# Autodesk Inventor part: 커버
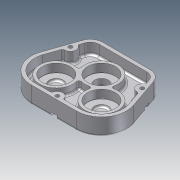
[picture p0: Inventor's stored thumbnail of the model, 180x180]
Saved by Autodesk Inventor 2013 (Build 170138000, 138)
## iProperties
Company: 한국ATC센터
Created: 2014-12
Part Number: 커버
Document SubType Name: Modeling
Designer: KYOUNG IL JANG
Density: 1 g/cm^3
Mass: 160.364 g
Surface Area: 512.085 cm^2
Volume: 160.364 cm^3
Material: 일반
Author: KYOUNG IL JANG
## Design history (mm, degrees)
sketch "스케치1"
  geometry: L1 (-66.565, -20.803)-(-47, 36); L2 (47, 36)-(66.565, -20.803); L3 (-32.527, -68.527)-(32.527, -68.527); L4 (-47, 36)-(47, 36); C1 r 28 at (0, 0); C2 r 18 at (-32.527, -32.527); C3 r 18 at (32.527, -32.527); A1 r 36 centre (-32.527, -32.527) between (-66.565, -20.803) and (-32.527, -68.527); A2 r 36 centre (32.527, -32.527) between (32.527, -68.527) and (66.565, -20.803); 2 further points
  constraints: 8 end point, 6 tangent, 5 centre point, 4 point on circle, 3 coincident, 2 equal radius, 1 equal length, 1 horizontal alignment, 1 midpoint, 1 vertical alignment
  dimensions: "d0" = 56 diameter of C1; "d1" = 36 diameter of C2; "d2" = 90 deg dimension on point (0, 0) C3.centre C2.centre; "d3" = 36 radius of A1; "d4" = 104.52691 distance between parallel lines of L3 L4 (derived); "d5" = 94 distance of L1.end L2.start; "d65" = 36 distance from line of point (0, 0) L4
extrude "돌출1" new body sketch "스케치1" distance "d6" = 25; taper "d7" = 0 deg
fillet "모깎기1" dims "d8" = 18
feature "쉘1" dims "d9" = 9, "d10" = 5
sketch "스케치2"
  geometry: C1 r 24 at (1.635, -63.527); C2 r 24 at (66.689, -63.527); C3 r 24 at (34.162, -31); 4 further points
  constraints: 4 coincident, 3 centre point, 1 equal radius
  dimensions: "d11" = 48 diameter of C3; "d12" = 48 diameter of C2
extrude "돌출2" join sketch "스케치2" distance "d13" = 11; taper "d14" = 0 deg
hole "구멍1" diameter "d17" = 20; stored, may be unused: countersink angle "d21" = 90 deg, drill point angle "d23" = 0 deg; dims "d15" = 10, "d16" = 10, "d18" = 6, "d19" = 40, "d20" = 12, "d22" = 3
hole "구멍2" diameter "d26" = 20; stored, may be unused: countersink angle "d30" = 90 deg, drill point angle "d32" = 0 deg; dims "d24" = 10, "d25" = 10, "d27" = 6, "d28" = 40, "d29" = 12, "d31" = 3
hole "구멍3" diameter "d35" = 20; stored, may be unused: countersink angle "d39" = 90 deg, drill point angle "d41" = 118 deg; dims "d33" = 10, "d34" = 10, "d36" = 6, "d37" = 40, "d38" = 12, "d40" = 3
sketch "스케치3"
  geometry: C1 r 15 at (0, 0); C2 r 20 at (0, 0); 1 further point
  constraints: 2 centre point, 2 coincident
  dimensions: "d42" = 40 diameter of C2; "d43" = 30 diameter of C1
extrude "돌출3" join sketch "스케치3" distance "d44" = 8; taper "d45" = 0 deg
feature "면 기울기1" dims angle "d46" = 10 deg
fillet "모깎기2" dims "d47" = 3
fillet "모깎기3" dims "d48" = 0.3
fillet "모깎기6" dims "d66" = 0.1
sketch "스케치4"
  geometry: L1 (-61.837, -22.432)-(-46.453, 22.233) reference; L2 (46.453, 22.233)-(61.837, -22.432) reference; L3 (32.527, -63.527)-(-32.527, -63.527) reference; L4 (-34.162, 31)-(34.162, 31) reference; A1 r 8 centre (51.7, 7) between (49.095, 14.564) and (54.305, -0.564); A2 r 8 centre (-51.7, 7) between (-54.305, -0.564) and (-49.095, 14.564); A3 r 8 centre (0, -63.527) between (8, -63.527) and (-8, -63.527)
  constraints: 8 point on line, 6 point on circle, 3 centre point, 2 equal radius, 1 horizontal alignment, 1 midpoint
  dimensions: "d49" = 8 radius of A1; "d51" = 24 distance from line of A2.centre L4
extrude "돌출4" join sketch "스케치4" stored distance "d52" = 8; taper "d53" = 0 deg
fillet "모깎기4" dims "d54" = 3
sketch "스케치5"
  geometry: A1 r 8 centre (-51.7, 7) between (-52.144, -0.988) and (-47.131, 13.567) reference; A2 r 8 centre (0, -63.527) between (7.697, -61.345) and (-7.697, -61.345) reference; A3 r 8 centre (51.7, 7) between (47.131, 13.567) and (52.144, -0.988) reference; 1 further point
hole "구멍4" sketch "스케치5" at (0, -63.527), (-51.7, 7), (51.7, 7) diameter "d55" = 5.5; stored, may be unused: countersink angle "d59" = 90 deg, drill point angle "d61" = 118 deg; dims "d56" = 6, "d57" = 9.5, "d58" = 5.4, "d60" = 3
sketch "스케치6"
  geometry: L1 (-51.181, 23.862)-(-66.565, -20.803) reference; L2 (66.565, -20.803)-(51.181, 23.862) reference; L3 (-32.527, -68.527)-(32.527, -68.527) reference; L4 (-50.153, 11.491)-(-54.881, 13.119); L5 (-53.247, 2.509)-(-57.974, 4.137); L6 (50.153, 11.491)-(54.881, 13.119); L7 (53.247, 2.509)-(57.974, 4.137); L8 (4.75, -63.527)-(4.75, -68.527); L9 (-4.75, -63.527)-(-4.75, -68.527); A1 r 4.75 centre (-51.7, 7) between (-54.994, 3.578) and (-52.188, 11.725) reference; A2 r 4.75 centre (51.7, 7) between (52.188, 11.725) and (54.994, 3.578) reference; A3 r 4.75 centre (0, -63.527) between (4.308, -65.527) and (-4.308, -65.527) reference; 1 further point
  constraints: 12 end point, 6 perpendicular, 6 point on circle, 6 point on line, 6 tangent
extrude "돌출5" cut sketch "스케치6" distance "d62" = 5.4; taper "d63" = 0 deg
fillet "모깎기5" dims "d64" = 3
node "솔리드1"
